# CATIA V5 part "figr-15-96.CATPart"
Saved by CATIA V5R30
Part number: Part1
Bounding box of the stored display mesh (mm): x -31.325 to 48, y -66.072 to 47.73, z 0 to 2
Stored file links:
  D:\PROJECTS\CATIA V56R 2020\Resources\Parts File\c15_catia_v5_6r2020_prt\figr-15-96.CATPart
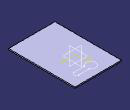
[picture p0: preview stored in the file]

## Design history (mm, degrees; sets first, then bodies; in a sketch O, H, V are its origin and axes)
SheetMetalParameters1: Thickness 2, BendRadius 4, KFactor 0.400515 {= log(min(100,max(20*SheetMetalParameters1.BendRadius,SheetMetalParameters1.Thickness)/SheetMetalParameters1.Thickness))/log(100)/2}, ReliefRadialLength 1, ReliefAxialLength 2, MinimumBendRadius 0
Body1 (main body)
  Sketch1 on xy-plane, origin (0, 0, 0), H (1, 0, 0), V (0, 1, 0)
    line L1 (-31.3255, 47.7299) -> (48, 47.7299)
    line L2 (48, 47.7299) -> (48, -66.0715)
    line L3 (48, -66.0715) -> (-31.3255, -66.0715)
    line L4 (-31.3255, -66.0715) -> (-31.3255, 47.7299)
    horizontal: L1 H, L3 H
    vertical: L2 V, L4 V
  Wall1: Thickness 2, Profile Sketch1, OffsetValue 0
  Sketch2 on face of Wall1, origin (0, 0, 2), H (1, 0, 0), V (0, 1, 0)
    construction line L1 (2.2258, 29) -> (27.2258, 29)
    point P1 (2.2258, 29)
    point P2 (27.2258, 29)
    line L2 (27.2258, 25) -> (9.154, 25)
    line L3 (9.154, 33) -> (27.2258, 33)
    arc A1 centre (2.2258, 29) radius 8 from (9.154, 25) to (9.154, 33) cw
    arc A2 centre (27.2258, 29) radius 4 from (27.2258, 33) to (27.2258, 25) cw
    radius A1 = 8
    radius A2 = 4
    distance P2 P1 = 25
    horizontal: L1 H
    tangency: A2 L2, A2 L3
    parallelism: L2 L3, L2 L1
